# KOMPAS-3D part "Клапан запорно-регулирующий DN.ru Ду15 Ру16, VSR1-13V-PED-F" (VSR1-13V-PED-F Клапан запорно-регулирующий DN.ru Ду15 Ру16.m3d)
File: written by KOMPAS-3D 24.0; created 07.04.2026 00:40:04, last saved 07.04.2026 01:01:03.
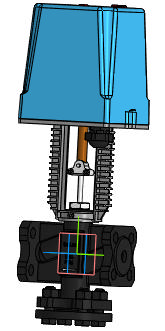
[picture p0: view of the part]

Document properties: Автор: R2D2; Полное имя файла: VSR1-13V-PED-F Клапан запорно-регулирующий DN.ru Ду15 Ру16.cdw

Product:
- Part/product: Клапан запорно-регулирующий DN.ru Ду15 Ру16  | designation VSR1-13V-PED-F
    Масса: 6.1
    Раздел спецификации: Прочие изделия
    Форматы листов документа: A3
    Примечание: D090-02883

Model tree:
1. Операция без истории:1  (labels: SHAPEOBJECT3D_ATTR_BUTT)

Expressions: VSR1-13V-PED-F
